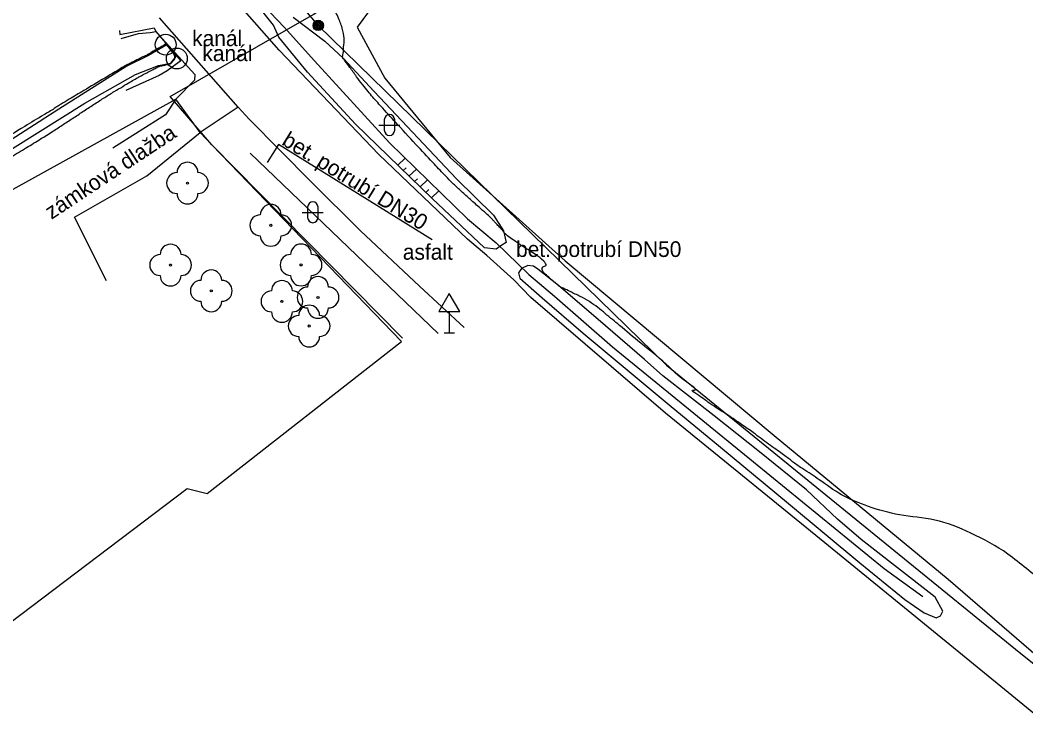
# Model space of a CAD drawing. Extents: x -478000 to -474772, y -1116847 to -1114124.
# Drawn here: x -477061.8 to -476965.5, y -1115085.9 to -1115018.8 of the extents above; entities that cross this region are included whole.
import ezdxf

# ---------------------------------------------------------------- set-up
doc = ezdxf.new("R2010")
doc.units = 0
for name, color, linetype in [('BodoveZnackyDopravniZnacky', 7, 'Continuous'), ('BodoveZnackySachtaKanalizacni', 7, 'Continuous'), ('BodoveZnackySloupy', 7, 'Continuous'), ('NadzemniVedeniSdelovaci', 7, 'Continuous'), ('ObPÚ', 7, 'Continuous'), ('OstatniRozhrani', 7, 'Continuous'), ('Ploty', 7, 'Continuous'), ('PopisneZnackyKultura', 7, 'Continuous'), ('PopisObjektu', 7, 'Continuous'), ('PopisPovrchu', 7, 'Continuous'), ('RozhraniKultur', 7, 'Continuous'), ('RozhraniVozovky', 7, 'Continuous'), ('Teren_HranaSvahu', 7, 'Continuous'), ('Teren_PataSvahu', 7, 'Continuous'), ('Vrstevnice_hlavni', 7, 'Continuous'), ('Vrstevnice_vedlejsi', 7, 'Continuous'), ('VstupNaPozemek', 7, 'Continuous'), ('VyskoveSrafy', 7, 'Continuous'), ('ZnackyStromu', 7, 'Continuous')]:
    doc.layers.add(name, color=color, linetype=linetype)

msp = doc.modelspace()

# ---------------------------------------------------------------- linework, layer by layer
at = {"layer": 'BodoveZnackyDopravniZnacky'}
for p, q in [((-477020.742, -1115046.666), (-477020.742, -1115048.706)), ((-477021.242, -1115048.706), (-477020.242, -1115048.706))]:
    msp.add_line(p, q, dxfattribs=at)
msp.add_lwpolyline([(-477021.742, -1115046.666), (-477019.742, -1115046.666), (-477020.742, -1115044.946)], close=True, dxfattribs=at)
at = {"layer": 'BodoveZnackySachtaKanalizacni'}
for centre in [(-477047.9, -1115021.11), (-477046.83, -1115022.43)]:
    msp.add_circle(centre, 1, dxfattribs=at)
at = {"layer": 'BodoveZnackySloupy'}
for radius in [0.5, 0.4, 0.3, 0.2, 0.1]:
    msp.add_circle((-477033.291, -1115019.258), radius, dxfattribs=at)
at = {"layer": 'NadzemniVedeniSdelovaci'}
msp.add_line((-477043.667, -1115007.336), (-477033.291, -1115019.258), dxfattribs=at)
msp.add_lwpolyline([(-477033.291, -1115019.258), (-476999.93, -1115051.795), (-476966.529, -1115079.016), (-476928.709, -1115109.384), (-476895.363, -1115135.649), (-476857.802, -1115165.882), (-476818.46, -1115197.071), (-476787.517, -1115222.228)], dxfattribs=at)
at = {"layer": 'ObPÚ'}
msp.add_lwpolyline([(-477231.42, -1115250.62), (-477154.22, -1115173.58), (-477134.18, -1115148.75), (-477133.16, -1115130.26), (-477132.09, -1115111.94), (-477138.91, -1115081.32), (-477119.74, -1115082.72), (-477097.23, -1115062.71), (-477080.55, -1115086.81), (-477072.47, -1115083.76), (-477045.85, -1115063.61), (-477043.93, -1115064.09), (-477025.31, -1115049.55), (-477043.48, -1115030.71), (-477047.46, -1115026.08), (-477033.7, -1115018.17), (-476933.96, -1114947.92), (-476834.35, -1114877.76), (-476714.64, -1114803.8), (-476602.93, -1114745.91), (-476491.34, -1114705.52), (-476390.17, -1114678.77), (-476300.68, -1114655.71)], dxfattribs=at)
at = {"layer": 'OstatniRozhrani'}
for p, q in [((-477048.86, -1115019.86), (-477045.113, -1115023.965)), ((-477045.113, -1115023.965), (-477045.15, -1115024.51)), ((-477045.15, -1115024.51), (-477046.94, -1115026.33)), ((-477046.94, -1115026.33), (-477047.926, -1115027.82)), ((-477047.926, -1115027.82), (-477052.975, -1115031.021)), ((-477040.95, -1115027.09), (-477044.6, -1115029.53)), ((-477016.248, -1115040.091), (-477013.132, -1115043.119))]:
    msp.add_line(p, q, dxfattribs=at)
for points in [[(-477052.31, -1115019.75), (-477052.28, -1115020.12), (-477049.01, -1115019.5)], [(-477049.01, -1115019.5), (-477048.86, -1115019.86)], [(-477053.577, -1115043.726), (-477056.618, -1115037.636), (-477049.712, -1115033.684), (-477044.6, -1115029.53)], [(-477021.815, -1115048.773), (-477039.806, -1115031.489)]]:
    msp.add_lwpolyline(points, dxfattribs=at)
at = {"layer": 'Ploty'}
msp.add_line((-477065.753, -1115036.725), (-477046.94, -1115026.33), dxfattribs=at)
msp.add_lwpolyline([(-477043.48, -1115030.71), (-477025.21, -1115049.23)], dxfattribs=at)
at = {"layer": 'PopisneZnackyKultura'}
for p, q in [((-477026.98, -1115028.311), (-477026.98, -1115029.311)), ((-477025.98, -1115028.311), (-477025.98, -1115029.311)), ((-477027.48, -1115028.811), (-477025.48, -1115028.811)), ((-477034.818, -1115037.168), (-477032.818, -1115037.168)), ((-477034.318, -1115036.668), (-477034.318, -1115037.668)), ((-477033.318, -1115036.668), (-477033.318, -1115037.668))]:
    msp.add_line(p, q, dxfattribs=at)
for centre, start, end in [((-477026.471, -1115028.303), 0, 180), ((-477026.471, -1115029.303), 180, 0), ((-477033.81, -1115036.66), 0, 180), ((-477033.81, -1115037.66), 180, 0)]:
    msp.add_arc(centre, 0.5, start, end, dxfattribs=at)
at = {"layer": 'PopisObjektu'}
for p, q in [((-477037.089, -1115030.659), (-477038.168, -1115032.399)), ((-477037.089, -1115030.659), (-477038.168, -1115032.399)), ((-477022.374, -1115039.79), (-477037.089, -1115030.659)), ((-477022.374, -1115039.79), (-477037.089, -1115030.659))]:
    msp.add_line(p, q, dxfattribs=at)
at = {"layer": 'RozhraniKultur'}
msp.add_lwpolyline([(-476977.493, -1114980.375), (-477007.129, -1115002.001), (-477014.915, -1115008.242), (-477024.119, -1115014.107), (-477027.941, -1115017.232), (-477029.578, -1115019.427), (-477026.9, -1115024.33), (-477020.646, -1115031.926), (-477009.657, -1115041.804), (-476989.625, -1115058.533), (-476972.959, -1115072.298), (-476959.884, -1115083.606), (-476949.57, -1115092.134), (-476936.86, -1115101.458), (-476916.801, -1115117.809), (-476898.41, -1115131.913), (-476893.29, -1115135.894), (-476884.407, -1115144.075), (-476873.818, -1115152.879), (-476869.38, -1115155.33)], dxfattribs=at)
at = {"layer": 'RozhraniVozovky'}
for p, q in [((-477039.9, -1115028.25), (-477033.981, -1115034.239)), ((-477033.981, -1115034.239), (-477029.236, -1115038.949)), ((-477029.236, -1115038.949), (-477023.593, -1115044.225)), ((-477023.593, -1115044.225), (-477019.316, -1115048.201))]:
    msp.add_line(p, q, dxfattribs=at)
for points in [[(-476865.295, -1115165.15), (-476877.91, -1115155.046), (-476889.001, -1115146.126), (-476898.45, -1115138.608), (-476912.991, -1115126.893), (-476925.609, -1115116.576), (-476934.243, -1115109.589), (-476945.7, -1115100.408), (-476959.339, -1115089.601), (-476971.594, -1115079.598), (-476985.634, -1115068.114), (-477000.032, -1115056.392), (-477012.922, -1115045.335), (-477014.574, -1115043.636), (-477017.158, -1115041.291), (-477019.005, -1115039.725), (-477027.483, -1115031.623), (-477037.022, -1115021.628), (-477042.231, -1115015.698), (-477046.885, -1115010.045)], [(-477039.9, -1115028.25), (-477040.95, -1115027.09), (-477048.51, -1115018.53)]]:
    msp.add_lwpolyline(points, dxfattribs=at)
at = {"layer": 'Teren_HranaSvahu'}
for p, q in [((-477052.175, -1115020.52), (-477050.512, -1115020.049)), ((-477050.512, -1115020.049), (-477049.375, -1115019.926)), ((-477049.375, -1115019.926), (-477048.86, -1115019.86)), ((-477048.86, -1115019.86), (-477046.466, -1115022.67)), ((-477046.466, -1115022.67), (-477047.774, -1115023.626)), ((-477047.774, -1115023.626), (-477048.526, -1115024.054)), ((-477048.526, -1115024.054), (-477051.718, -1115025.509))]:
    msp.add_line(p, q, dxfattribs=at)
msp.add_lwpolyline([(-477035.707, -1115018.475), (-477032.661, -1115020.769), (-477030.906, -1115022.389), (-477027.947, -1115025.584), (-477020.066, -1115033.955), (-477016.5, -1115037.431), (-477015.559, -1115038.929), (-477015.304, -1115040.063), (-477015.708, -1115040.303), (-477016.242, -1115040.684), (-477017.369, -1115040.576), (-477022.381, -1115035.841), (-477029.723, -1115028.731), (-477034.336, -1115023.744), (-477037.062, -1115020.38), (-477037.585, -1115019.228), (-477041.218, -1115014.655)], dxfattribs=at)
msp.add_lwpolyline([(-477005.774, -1115048.027), (-477010.278, -1115044.187), (-477012.255, -1115042.62), (-477012.695, -1115042.332), (-477013.222, -1115042.252), (-477013.828, -1115042.55), (-477014.11, -1115042.948), (-477014.002, -1115043.483), (-477011.852, -1115045.345), (-477007.91, -1115048.742), (-476999.695, -1115055.616), (-476994.787, -1115059.668), (-476988.263, -1115065.069), (-476981.432, -1115070.738), (-476977.131, -1115074.256), (-476975.274, -1115075.534), (-476974.108, -1115076.008), (-476973.702, -1115075.822), (-476973.497, -1115075.364), (-476974.213, -1115074.026), (-476978.122, -1115071.011), (-476981.313, -1115068.496), (-476983.575, -1115066.56), (-476986.53, -1115063.741), (-476991.025, -1115060.103), (-476995.39, -1115056.669), (-477000.307, -1115052.817), (-477002.036, -1115051.25)], close=True, dxfattribs=at)
at = {"layer": 'Teren_PataSvahu'}
for points in [[(-477047.805, -1115006.016), (-477041.728, -1115013.393), (-477040.206, -1115015.068), (-477039.547, -1115015.621), (-477037.87, -1115018.041), (-477036.57, -1115019.43), (-477033.66, -1115022.664), (-477026.482, -1115030.497), (-477018.989, -1115037.803), (-477016.248, -1115040.091)], [(-477064.756, -1115032.395), (-477055.652, -1115026.703), (-477050.782, -1115023.971), (-477048.583, -1115023.109), (-477047.416, -1115022.87), (-477046.913, -1115022.248), (-477047.8, -1115021.106), (-477049.557, -1115022.132), (-477051.634, -1115023.162), (-477058.143, -1115027.298), (-477067.397, -1115033.22)], [(-477013.132, -1115043.119), (-477010.662, -1115045.21), (-477005.106, -1115050.049), (-476991.599, -1115061.056), (-476979.115, -1115071.301), (-476975.404, -1115073.978)]]:
    msp.add_lwpolyline(points, dxfattribs=at)
at = {"layer": 'Vrstevnice_hlavni'}
for points in [[(-477017.894, -1115036.673), (-477018.831, -1115035.848), (-477019.673, -1115035.079), (-477020.422, -1115034.367), (-477021.076, -1115033.712), (-477022.168, -1115032.564), (-477023.697, -1115030.923), (-477025.662, -1115028.788), (-477027.122, -1115027.188), (-477028.074, -1115026.123), (-477028.52, -1115025.593), (-477029.034, -1115024.943), (-477029.617, -1115024.173), (-477030.269, -1115023.282), (-477030.708, -1115022.682), (-477030.934, -1115022.374), (-477030.946, -1115022.357), (-477030.928, -1115022.077), (-477030.878, -1115021.535), (-477030.797, -1115020.729), (-477030.934, -1115019.788), (-477031.286, -1115018.713), (-477031.856, -1115017.503), (-477032.238, -1115016.683), (-477032.433, -1115016.253), (-477032.44, -1115016.214), (-477032.443, -1115016.185), (-477032.441, -1115016.166), (-477032.435, -1115016.159), (-477032.431, -1115016.153), (-477032.428, -1115016.149), (-477032.426, -1115016.147), (-477032.373, -1115016.122), (-477032.267, -1115016.074), (-477032.11, -1115016.003), (-477031.64, -1115015.843), (-477030.858, -1115015.596), (-477029.763, -1115015.26), (-477028.959, -1115014.975), (-477028.444, -1115014.74), (-477028.219, -1115014.556), (-477028.06, -1115014.364), (-477027.968, -1115014.165), (-477027.943, -1115013.958), (-477027.674, -1115013.593), (-477027.161, -1115013.071), (-477026.405, -1115012.392), (-477025.889, -1115011.927), (-477025.616, -1115011.677), (-477025.583, -1115011.642), (-477025.534, -1115011.602), (-477025.469, -1115011.556), (-477025.387, -1115011.505), (-477025.033, -1115011.201), (-477024.407, -1115010.643), (-477023.509, -1115009.833), (-477022.858, -1115009.263), (-477022.455, -1115008.935), (-477022.299, -1115008.848), (-477021.991, -1115008.674), (-477021.533, -1115008.413), (-477020.923, -1115008.064), (-477020.468, -1115007.826), (-477020.167, -1115007.697), (-477020.021, -1115007.678), (-477019.883, -1115007.635), (-477019.754, -1115007.567), (-477019.633, -1115007.475), (-477019.398, -1115007.325), (-477019.047, -1115007.117), (-477018.115, -1115006.584)], [(-476873.251, -1115143.677), (-476873.507, -1115142.01), (-476873.554, -1115139.102), (-476873.522, -1115134.12), (-476873.41, -1115127.063), (-476873.808, -1115122.086), (-476874.717, -1115119.19), (-476876.136, -1115118.374), (-476877.354, -1115117.171), (-476878.371, -1115115.579), (-476879.185, -1115113.6), (-476882.364, -1115111.475), (-476887.908, -1115109.205), (-476895.815, -1115106.789), (-476902.242, -1115103.761), (-476907.186, -1115100.12), (-476910.649, -1115095.867), (-476913.66, -1115091.883), (-476916.218, -1115088.167), (-476918.324, -1115084.72), (-476919.725, -1115082.379), (-476920.421, -1115081.145), (-476920.412, -1115081.017), (-476920.426, -1115080.932), (-476920.462, -1115080.891), (-476920.521, -1115080.893), (-476920.576, -1115080.895), (-476920.627, -1115080.896), (-476920.674, -1115080.898), (-476921.736, -1115080.799), (-476923.814, -1115080.599), (-476926.907, -1115080.3), (-476932.302, -1115079.591), (-476940, -1115078.472), (-476950, -1115076.944), (-476957.876, -1115075.006), (-476963.629, -1115072.657), (-476967.259, -1115069.897), (-476970.802, -1115067.892), (-476974.259, -1115066.643), (-476977.631, -1115066.149), (-476980.601, -1115065.341), (-476983.17, -1115064.218), (-476985.338, -1115062.781), (-476986.878, -1115061.747), (-476987.79, -1115061.118), (-476988.074, -1115060.892), (-476988.478, -1115060.587), (-476989.003, -1115060.204), (-476989.648, -1115059.743), (-476990.332, -1115059.246), (-476991.055, -1115058.714), (-476991.817, -1115058.146), (-476992.891, -1115057.395), (-476994.277, -1115056.46), (-476995.976, -1115055.343), (-476997.039, -1115054.593), (-476997.464, -1115054.21), (-476997.254, -1115054.195), (-476998.009, -1115053.437), (-476999.729, -1115051.937), (-477002.416, -1115049.693), (-477004.444, -1115048.001), (-477005.814, -1115046.86), (-477006.527, -1115046.27), (-477007.324, -1115045.723), (-477008.206, -1115045.221), (-477009.173, -1115044.763), (-477009.833, -1115044.445), (-477010.186, -1115044.267), (-477010.232, -1115044.228), (-477010.318, -1115044.158), (-477010.443, -1115044.058), (-477010.608, -1115043.927), (-477010.866, -1115043.703), (-477011.219, -1115043.389), (-477011.666, -1115042.982), (-477011.859, -1115042.654), (-477011.796, -1115042.405), (-477011.479, -1115042.235), (-477011.695, -1115041.846), (-477012.445, -1115041.236), (-477013.729, -1115040.407), (-477014.642, -1115039.799), (-477015.184, -1115039.41), (-477015.355, -1115039.241), (-477015.476, -1115039.117), (-477015.545, -1115039.038), (-477015.564, -1115039.003), (-477015.672, -1115038.875), (-477015.869, -1115038.653), (-477016.157, -1115038.339), (-477016.405, -1115038.07), (-477016.615, -1115037.849), (-477016.786, -1115037.674), (-477017.213, -1115037.282), (-477017.894, -1115036.673)]]:
    msp.add_spline(points, degree=3, dxfattribs=at)
at = {"layer": 'Vrstevnice_vedlejsi'}
for points in [[(-477047.764, -1115021.143), (-477047.807, -1115021.087), (-477047.84, -1115021.051), (-477047.862, -1115021.035), (-477047.874, -1115021.038), (-477048.066, -1115021.148), (-477048.439, -1115021.365), (-477048.993, -1115021.689), (-477049.369, -1115021.906), (-477049.566, -1115022.018), (-477049.585, -1115022.024), (-477049.603, -1115022.032), (-477049.62, -1115022.044), (-477049.636, -1115022.059), (-477049.869, -1115022.179), (-477050.319, -1115022.405), (-477050.986, -1115022.735), (-477051.44, -1115022.961), (-477051.68, -1115023.08), (-477051.707, -1115023.094), (-477052.394, -1115023.504), (-477053.742, -1115024.308), (-477055.751, -1115025.507), (-477057.143, -1115026.339), (-477057.916, -1115026.803), (-477058.072, -1115026.899), (-477058.233, -1115027.001), (-477058.398, -1115027.108), (-477058.569, -1115027.221), (-477059.569, -1115027.831), (-477061.399, -1115028.936), (-477064.059, -1115030.537), (-477065.922, -1115031.657), (-477066.987, -1115032.295), (-477067.255, -1115032.451), (-477067.533, -1115032.618), (-477067.822, -1115032.796), (-477068.122, -1115032.984), (-477068.88, -1115033.421), (-477070.096, -1115034.105), (-477071.77, -1115035.038), (-477072.989, -1115035.726), (-477073.751, -1115036.168), (-477074.057, -1115036.365), (-477074.333, -1115036.554), (-477074.579, -1115036.736), (-477074.794, -1115036.91), (-477075.324, -1115037.31), (-477076.168, -1115037.936), (-477077.327, -1115038.79), (-477078.203, -1115039.464), (-477078.798, -1115039.959), (-477079.111, -1115040.275), (-477079.455, -1115040.634), (-477079.831, -1115041.038), (-477080.238, -1115041.485), (-477080.787, -1115042.043), (-477081.476, -1115042.712), (-477082.307, -1115043.493), (-477083.019, -1115044.159), (-477083.61, -1115044.71), (-477084.082, -1115045.147), (-477084.651, -1115045.674), (-477085.315, -1115046.29), (-477086.075, -1115046.995), (-477086.782, -1115047.662), (-477087.437, -1115048.292), (-477088.038, -1115048.885), (-477088.682, -1115049.509), (-477089.369, -1115050.164), (-477090.097, -1115050.851), (-477090.791, -1115051.495), (-477091.451, -1115052.094), (-477092.076, -1115052.649), (-477092.683, -1115053.204), (-477093.273, -1115053.758), (-477093.846, -1115054.312), (-477094.405, -1115054.864), (-477094.949, -1115055.416), (-477095.479, -1115055.966), (-477096.073, -1115056.582), (-477096.731, -1115057.264), (-477097.453, -1115058.011), (-477098.084, -1115058.661), (-477098.627, -1115059.215), (-477099.079, -1115059.673), (-477099.591, -1115060.191), (-477100.163, -1115060.77), (-477100.794, -1115061.411), (-477101.243, -1115061.866), (-477101.509, -1115062.137), (-477101.593, -1115062.222), (-477101.981, -1115062.587), (-477102.673, -1115063.234), (-477103.67, -1115064.162), (-477104.352, -1115064.774), (-477104.719, -1115065.07)], [(-477108.024, -1115073.453), (-477107.41, -1115072.982), (-477106.961, -1115072.629), (-477106.676, -1115072.395), (-477106.556, -1115072.278), (-477106.091, -1115071.757), (-477105.281, -1115070.832), (-477104.126, -1115069.502), (-477103.309, -1115068.574), (-477102.828, -1115068.046), (-477102.685, -1115067.92), (-477102.316, -1115067.626), (-477101.72, -1115067.165), (-477100.898, -1115066.537), (-477100.184, -1115065.97), (-477099.579, -1115065.464), (-477099.081, -1115065.02), (-477098.73, -1115064.701), (-477098.524, -1115064.509), (-477098.465, -1115064.444), (-477098.01, -1115063.889), (-477097.162, -1115062.844), (-477095.919, -1115061.311), (-477094.978, -1115060.158), (-477094.339, -1115059.385), (-477094.002, -1115058.992), (-477093.57, -1115058.494), (-477093.044, -1115057.889), (-477092.423, -1115057.178), (-477091.967, -1115056.663), (-477091.675, -1115056.343), (-477091.547, -1115056.218), (-477091.414, -1115056.093), (-477091.276, -1115055.968), (-477091.133, -1115055.843), (-477090.09, -1115054.841), (-477088.145, -1115052.963), (-477085.299, -1115050.207), (-477083.328, -1115048.299), (-477082.232, -1115047.238), (-477082.012, -1115047.025), (-477081.803, -1115046.81), (-477081.606, -1115046.593), (-477081.422, -1115046.376), (-477080.916, -1115045.76), (-477080.09, -1115044.745), (-477078.942, -1115043.332), (-477078.165, -1115042.381), (-477077.759, -1115041.889), (-477077.722, -1115041.859), (-477077.193, -1115041.444), (-477076.171, -1115040.644), (-477074.656, -1115039.459), (-477073.586, -1115038.623), (-477072.96, -1115038.136), (-477072.779, -1115037.999), (-477071.961, -1115037.49), (-477070.508, -1115036.61), (-477068.419, -1115035.359), (-477066.799, -1115034.381), (-477065.649, -1115033.675), (-477064.968, -1115033.243), (-477064.004, -1115032.647), (-477062.756, -1115031.889), (-477061.226, -1115030.967), (-477059.874, -1115030.136), (-477058.7, -1115029.396), (-477057.706, -1115028.747), (-477056.705, -1115028.092), (-477055.698, -1115027.432), (-477054.685, -1115026.767), (-477053.73, -1115026.157), (-477052.836, -1115025.601), (-477052, -1115025.101), (-477051.326, -1115024.7), (-477050.814, -1115024.399), (-477050.463, -1115024.197), (-477050.058, -1115023.975), (-477049.6, -1115023.733), (-477049.089, -1115023.47), (-477048.739, -1115023.29), (-477048.551, -1115023.192), (-477048.525, -1115023.177), (-477048.392, -1115023.144), (-477048.151, -1115023.091), (-477047.802, -1115023.02), (-477047.557, -1115022.962), (-477047.416, -1115022.917), (-477047.38, -1115022.886), (-477047.304, -1115022.801), (-477047.188, -1115022.663), (-477047.034, -1115022.472), (-477047.024, -1115022.224), (-477047.159, -1115021.92), (-477047.44, -1115021.559), (-477047.642, -1115021.3), (-477047.764, -1115021.143)]]:
    msp.add_spline(points, degree=3, dxfattribs=at)
at = {"layer": 'VstupNaPozemek'}
for p, q in [((-477044.6, -1115029.53), (-477046.94, -1115026.33)), ((-477043.48, -1115030.71), (-477044.6, -1115029.53))]:
    msp.add_line(p, q, dxfattribs=at)
at = {"layer": 'VyskoveSrafy'}
for p, q in [((-477025.684, -1115032.642), (-477024.971, -1115031.97)), ((-477025.145, -1115033.164), (-477024.86, -1115032.896)), ((-477024.606, -1115033.687), (-477023.896, -1115033.019)), ((-477024.066, -1115034.209), (-477023.783, -1115033.942)), ((-477023.527, -1115034.731), (-477022.821, -1115034.067)), ((-477022.988, -1115035.254), (-477022.706, -1115034.988)), ((-477022.448, -1115035.776), (-477021.746, -1115035.115))]:
    msp.add_line(p, q, dxfattribs=at)
at = {"layer": 'ZnackyStromu'}
for centre in [(-477045.817, -1115034.366), (-477037.841, -1115038.409), (-477047.434, -1115042.218), (-477034.938, -1115042.207), (-477043.536, -1115044.688), (-477036.771, -1115045.699), (-477033.314, -1115045.321), (-477034.166, -1115048.058)]:
    msp.add_circle(centre, 0.1, dxfattribs=at)
for centre, start, end in [((-477045.817, -1115033.366), 0, 180), ((-477046.817, -1115034.366), 90, 270), ((-477044.817, -1115034.366), 270, 90), ((-477045.817, -1115035.366), 180, 0), ((-477037.841, -1115037.409), 0, 180), ((-477038.841, -1115038.409), 90, 270), ((-477036.841, -1115038.409), 270, 90), ((-477047.434, -1115041.218), 0, 180), ((-477037.841, -1115039.409), 180, 0), ((-477034.938, -1115041.207), 0, 180), ((-477048.434, -1115042.218), 90, 270), ((-477046.434, -1115042.218), 270, 90), ((-477035.938, -1115042.207), 90, 270), ((-477033.938, -1115042.207), 270, 90), ((-477047.434, -1115043.218), 180, 0), ((-477043.536, -1115043.688), 0, 180), ((-477034.938, -1115043.207), 180, 0), ((-477044.536, -1115044.688), 90, 270), ((-477042.536, -1115044.688), 270, 90), ((-477036.771, -1115044.699), 0, 180), ((-477033.314, -1115044.321), 0, 180), ((-477037.771, -1115045.699), 90, 270), ((-477035.771, -1115045.699), 270, 90), ((-477034.314, -1115045.321), 90, 270), ((-477032.314, -1115045.321), 270, 90), ((-477043.536, -1115045.688), 180, 0), ((-477034.166, -1115047.058), 0, 180), ((-477036.771, -1115046.699), 180, 0), ((-477035.166, -1115048.058), 90, 270), ((-477033.314, -1115046.321), 180, 0), ((-477033.166, -1115048.058), 270, 90), ((-477034.166, -1115049.058), 180, 0)]:
    msp.add_arc(centre, 1, start, end, dxfattribs=at)

# ---------------------------------------------------------------- texts
at = {"layer": 'PopisObjektu'}
for s, p in [('kanál', (-477045.369, -1115021.248)), ('kanál', (-477044.388, -1115022.682)), ('bet. potrubí DN50', (-477014.351, -1115041.442))]:
    msp.add_text(s, height=1.5, dxfattribs=at).set_placement(p)
msp.add_text('bet. potrubí DN30', height=1.5, rotation=328.29857, dxfattribs=at).set_placement((-477036.885, -1115030.627))
msp.add_text('bet. potrubí DN30', height=1.5, rotation=328.29857, dxfattribs=at).set_placement((-477036.885, -1115030.627))
at = {"layer": 'PopisPovrchu'}
msp.add_text('zámková dlažba', height=1.5, rotation=33.49518, dxfattribs=at).set_placement((-477058.84, -1115037.894))
msp.add_text('asfalt', height=1.5, dxfattribs=at).set_placement((-477025.196, -1115041.709))

doc.saveas('drawing.dxf')
